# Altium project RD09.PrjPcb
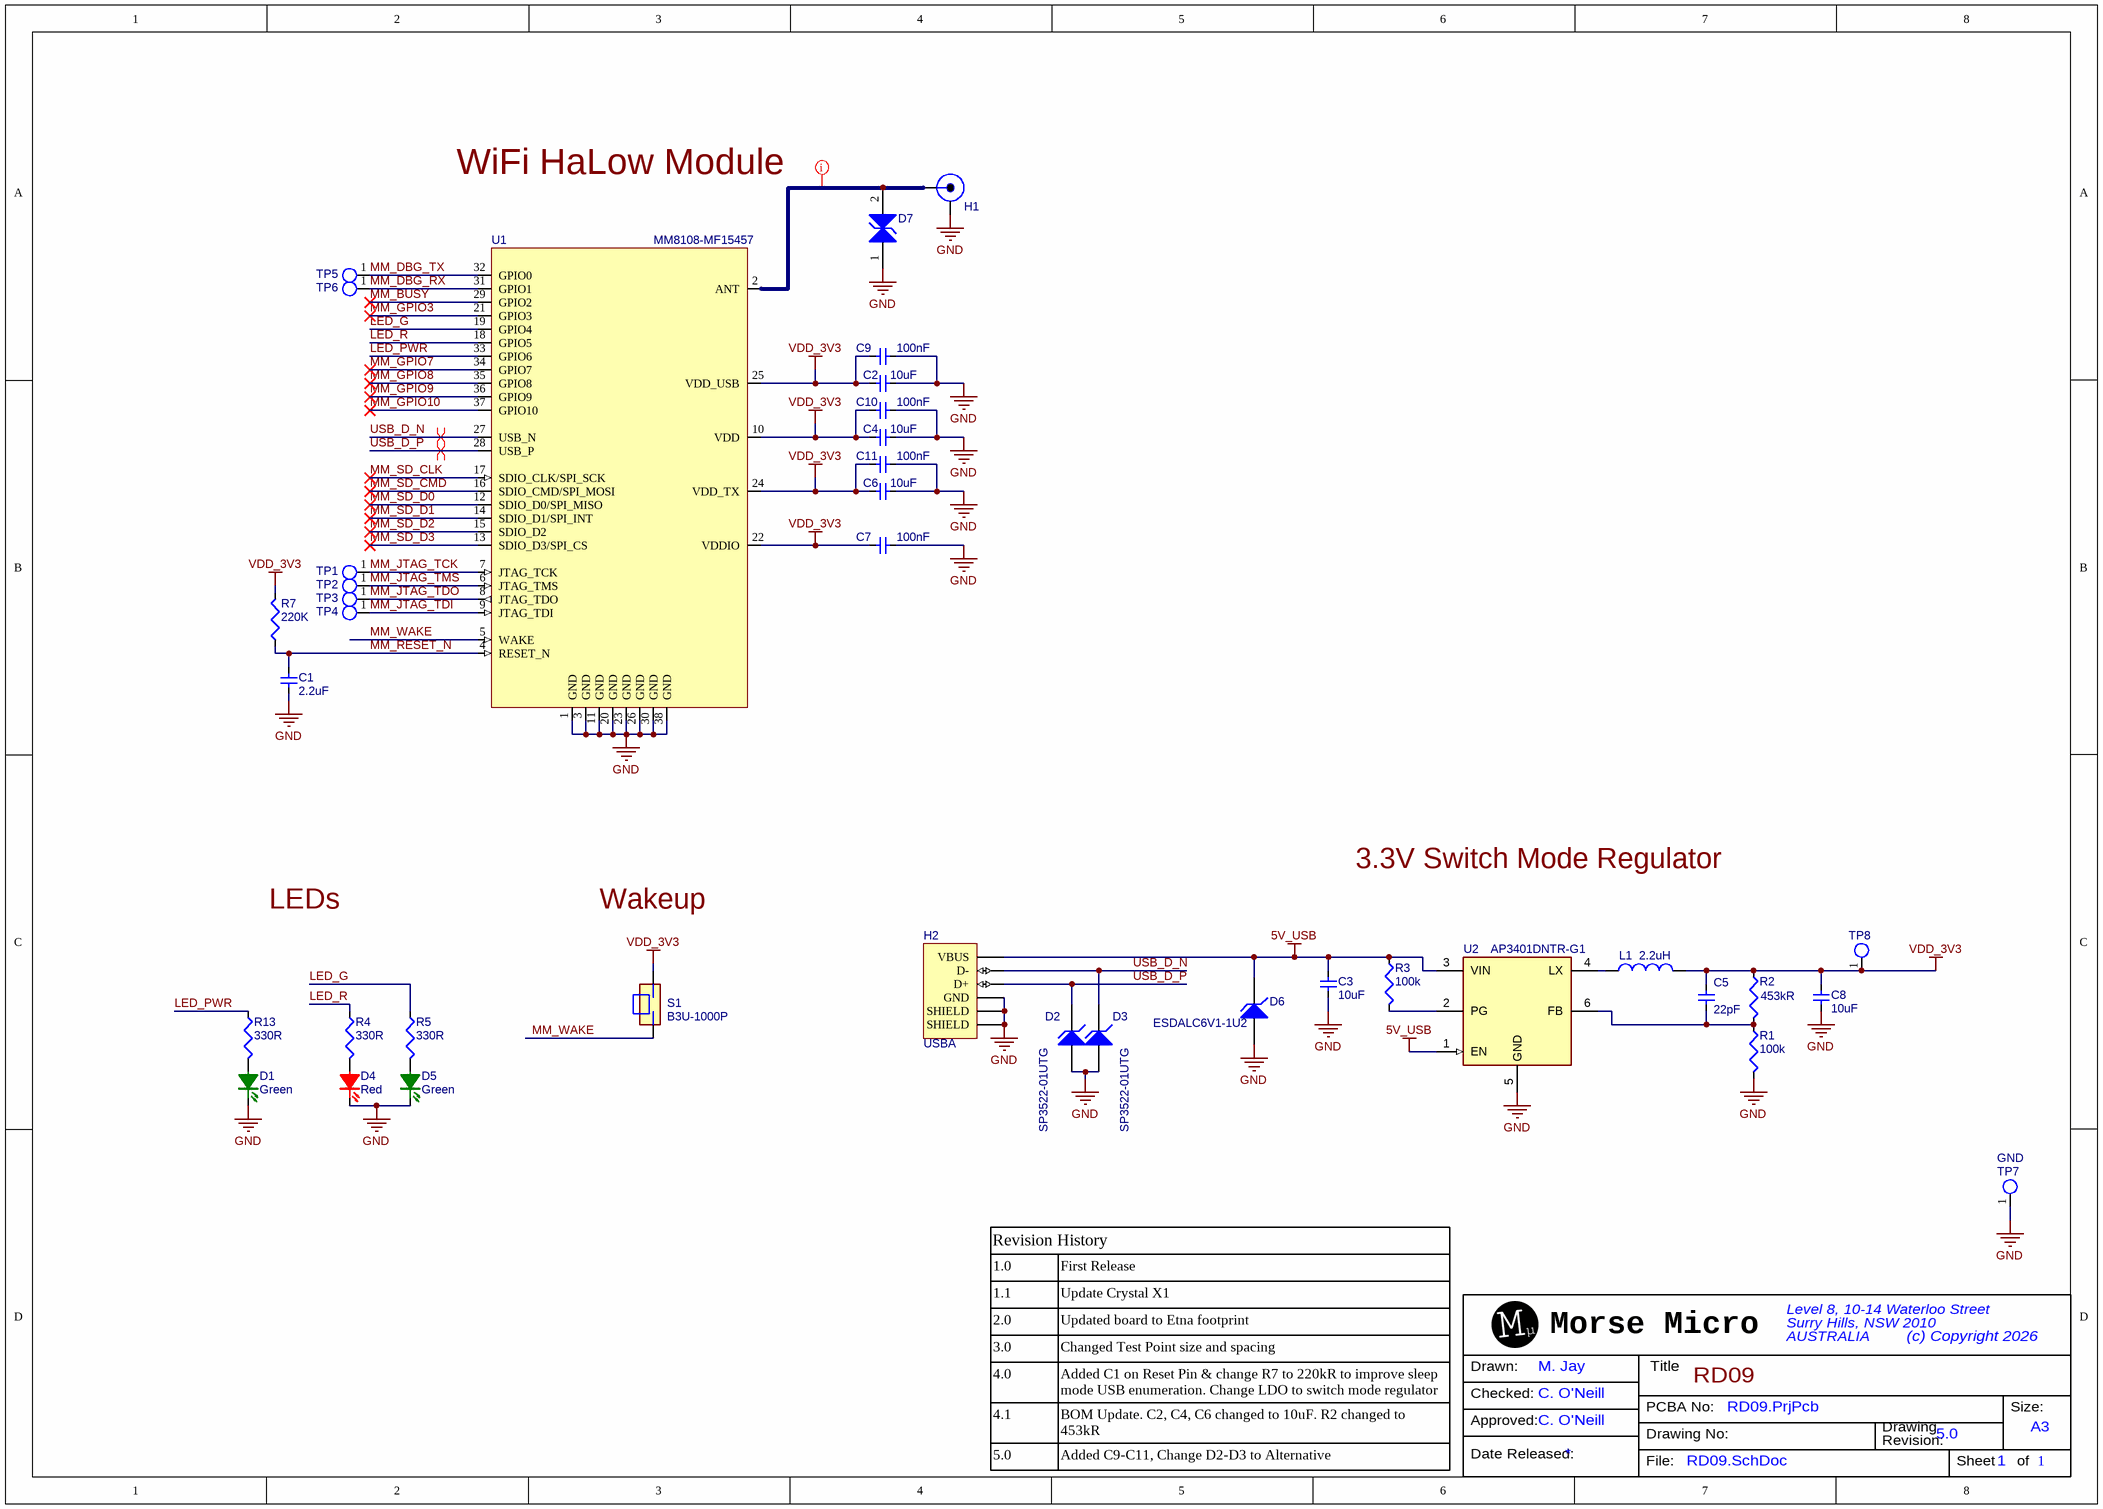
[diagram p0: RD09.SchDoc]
ApprovedBy: C. O'Neill; CheckedBy: C. O'Neill; DrawnBy: M. Jay; Project: RD09; Revision: 5.0
1 sheet, 39 parts. Net scope: global (net labels, ports and power ports of the same name join across sheets).
Board file: RD09.PcbDoc

## Sheet RD09.SchDoc: RD09
size A3; SheetNumber: 1; SheetTotal: 1; PageSetup: Record=PageOptions¦CenterHorizontal=True¦CenterVertical=True¦PrintScale=1.04¦XCorrection=1.00¦YCorrection=1.00¦PrintKind=0¦BorderSize=5000000¦LeftOffset=0¦BottomOffset=0¦Orientation=2¦PaperLength=1000¦PaperWidth=1000¦Scale=100¦PaperSource=7¦PrintQuality=-4¦MediaType=1¦DitherType=10¦PaperKind=A3¦PrintScaleMode=1

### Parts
C1  value 2.2uF  [0402_cap_rnd]  (hidden comment: GRM155R61E225ME15D)
C2  value 10uF  [0402_cap_rnd]  (hidden comment: CL05A106MP5NUNC)
C3  value 10uF  [0603_cap_rnd]  (hidden comment: GRM188R61E106MA73J)
C4  value 10uF  [0402_cap_rnd]  (hidden comment: CL05A106MP5NUNC)
C5  value 22pF  [0402_cap]  (hidden comment: CGA2B2NP01H220J050BA)
C6  value 10uF  [0402_cap_rnd]  (hidden comment: CL05A106MP5NUNC)
C7  value 100nF  [0402_cap_rnd]  (hidden comment: C0402C104K8RACTU)
C8  value 10uF  [0603_cap_rnd]  (hidden comment: GRM188R61E106MA73J)
C9  value 100nF  [0402_cap_rnd]  (hidden comment: C0402C104K8RACTU)
C10  value 100nF  [0402_cap_rnd]  (hidden comment: C0402C104K8RACTU)
C11  value 100nF  [0402_cap_rnd]  (hidden comment: C0402C104K8RACTU)
D1  value Green  [LED_0402_GREEN]  (hidden comment: XZVGR68W-3)
D2  SP3522-01UTG  [SP3522-01UTG-Footprint]
D3  SP3522-01UTG  [SP3522-01UTG-Footprint]
D4  value Red  [LED_0402_RED]  (hidden comment: LED_R)
D5  value Green  [LED_0402_GREEN]  (hidden comment: LED_G)
D6  ESDALC6V1-1U2  [0201_DIODE]
D7  ESD103B102ELE6327XTMA1  [INF-TSLP-2-20_V]  (value not drawn)
H1  142-0761-861  [SMA_EMERSON_142_0761_861]  (value not drawn)
H2  USBA  [USBA_BOARD_INLINE]
L1  value 2.2uH  [INDC2112X06N]  (hidden comment: LQM21PN2R2MGHL)
R1  value 100k  [0402_res_rnd]  (hidden comment: RC0402FR-07100KL)
R2  value 453kR  [0402_res]  (hidden comment: CRCW0402453KFKEDC)
R3  value 100k  [0402_res_rnd]  (hidden comment: RC0402FR-07100KL)
R4  value 330R  [0201_res_rnd]  (hidden comment: RES)
R5  value 330R  [0201_res_rnd]  (hidden comment: RES)
R7  value 220K  [0201_res_rnd]  (hidden comment: RC0201FR-07220KL)
R13  value 330R  [0201_res_rnd]  (hidden comment: RC0201FR-07330RL)
S1  B3U-1000P  [B3U-1000P]
TP1  PAD0035  [TP_40_SMT]  (value not drawn)
TP2  PAD0035  [TP_40_SMT]  (value not drawn)
TP3  PAD0035  [TP_40_SMT]  (value not drawn)
TP4  PAD0035  [TP_40_SMT]  (value not drawn)
TP5  PAD0035  [TP_40_SMT]  (value not drawn)
TP6  PAD0035  [TP_40_SMT]  (value not drawn)
TP7  PAD0035  [TP_40_SMT]  (value not drawn)
TP8  PAD0035  [TP_40_SMT]  (value not drawn)
U1  value MM8108-MF15457  [MF15]  (hidden comment: MM8108-MF15)
U2  AP3401DNTR-G1  [AP3401DNTR-G1-Footprint-1]

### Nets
5V_USB: C3.1 D6.K H2.1(VBUS) R3.1 U2.1(EN) U2.3(VIN)
GND: C1.2 C2.2 C3.2 C4.2 C6.2 C7.2 C8.2 C9.2 C10.2 C11.2 D1.K D2.A D3.A D4.K D5.K D6.A D7.1(C) H1.2 H2.4(GND) H2.5(SHIELD) H2.6(SHIELD) R1.2 TP7.1 U1.1(GND) U1.3(GND) U1.11(GND) U1.20(GND) U1.23(GND) U1.26(GND) U1.30(GND) U1.38(GND) U2.5(GND)
VDD_3V3: C2.1 C4.1 C5.1 C6.1 C7.1 C8.1 C9.1 C10.1 C11.1 L1.2 R2.1 R7.2 S1.2 TP8.1 U1.10(VDD) U1.22(VDDIO) U1.24(VDD_TX) U1.25(VDD_USB)
LED_G: R5.1 U1.19(GPIO4)
LED_PWR: R13.1 U1.33(GPIO6)
LED_R: R4.1 U1.18(GPIO5)
MM_BUSY: U1.29(GPIO2)
MM_DBG_RX: TP6.1 U1.31(GPIO1)
MM_DBG_TX: TP5.1 U1.32(GPIO0)
MM_GPIO3: U1.21(GPIO3)
MM_GPIO7: U1.34(GPIO7)
MM_GPIO8: U1.35(GPIO8)
MM_GPIO9: U1.36(GPIO9)
MM_GPIO10: U1.37(GPIO10)
MM_JTAG_TCK: TP1.1 U1.7(JTAG_TCK)
MM_JTAG_TDI: TP4.1 U1.9(JTAG_TDI)
MM_JTAG_TDO: TP3.1 U1.8(JTAG_TDO)
MM_JTAG_TMS: TP2.1 U1.6(JTAG_TMS)
MM_RESET_N: C1.1 R7.1 U1.4(RESET_N)
MM_SD_CLK: U1.17(SDIO_CLK/SPI_SCK)
MM_SD_CMD: U1.16(SDIO_CMD/SPI_MOSI)
MM_SD_D0: U1.12(SDIO_D0/SPI_MISO)
MM_SD_D1: U1.14(SDIO_D1/SPI_INT)
MM_SD_D2: U1.15(SDIO_D2)
MM_SD_D3: U1.13(SDIO_D3/SPI_CS)
MM_WAKE: S1.1 U1.5(WAKE)
USB_D_N: D3.K H2.2(D-) U1.27(USB_N)
USB_D_P: D2.K H2.3(D+) U1.28(USB_P)
NetC5_2: C5.2 R1.1 R2.2 U2.6(FB)
NetD1_A: D1.A R13.2
NetD4_A: D4.A R4.2
NetD5_A: D5.A R5.2
NetD7_2: D7.2(C) H1.1 U1.2(ANT)
NetL1_1: L1.1 U2.4(LX)
NetR3_2: R3.2 U2.2(PG)

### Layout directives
net class RF-Net: NetD7_2
differential pair; differential pair class DIFF_90: USB_D_N, USB_D_P

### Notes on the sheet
- WiFi HaLow Module
- LEDs
- Wakeup
- 3.3V Switch Mode Regulator
- (near TP7) GND
- Revision History
- 1.0
- 1.1
- First Release
- Update Crystal X1
- 2.0
- 3.0
- 4.0
- Updated board to Etna footprint
- Changed Test Point size and spacing
- Added C1 on Reset Pin & change R7 to 220kR to improve sleep mode USB enumeration. Change LDO to switch mode regulator
- 4.1
- BOM Update. C2, C4, C6 changed to 10uF. R2 changed to 453kR
- 5.0
- Added C9-C11, Change D2-D3 to Alternative

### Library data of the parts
C1 = CAP0055-14: CAP CER 2.2UF 25V ±20% X5R 0402; Generic Allowed: Yes; Subtype: Ceramic
C2 C4 C6 = CAP0268-1: Ceramic Capacitor, Multilayer, Ceramic, 10V, 20% +Tol, 20% -Tol, X5R, 15% TC, 10uF, Surface Mount, 0402; Generic Allowed: Yes
C3 C8 = CAP0197-10: CAP CER 10UF 25V ±20% X5R 0603; Subtype: Ceramic; Generic Allowed: Yes
C5 = CAP0017-14: CAP CER 22PF 50V ±5% C0G/NP0 0402; Generic Allowed: Yes; Subtype: Ceramic
C7 C9-C11 = CAP0025-15: CAP CER 100NF 10V ±10% X7R 0402; Generic Allowed: Yes; Subtype: Ceramic
D1 = DIO0053-7: LED GREEN 0402 SMD; Voltage: 2.0V; Generic Allowed: Yes
D2 D3 = DIO0091-2: ESD protection diodes / TVS diodes; LITTELFUSE; SP3522-01UTG; Surface Mount 0201
D4 = DIO0052-9: LED RED 0402 SMD; Generic Allowed: Yes; Voltage: 1.95V
D5 = DIO0053-7: LED GREEN 0402 SMD; Generic Allowed: Yes; Voltage: 2.0V
D6 = DIO0043-5: TVS DIODE 3VWM ST020; Generic Allowed: No; Voltage: 3V; Power: 20W
D7 = DIO0089-8: ESD103B102 Series 1 Line 15 V 0.2pF Bi-Direction TVS Protection Device-TSLP-2-20
H1 = JCK0001-4: Conn, SMA Jack 50 Ohm PCB Edge Mount Gold, RoHS; Generic Allowed: No
H2 = PLG0003-1: USB Connector, 4 Contact(s), Male, Right Angle, Surface Mount Terminal, Locking; Generic Allowed: YES
L1 = IND0084-2: FIXED IND 2.2uH 1.3A 156 MOHM 0805 ±20%; SubType: Multilayer; Generic Allowed: Yes
R1 R3 = RES0044-14: RES SMD 100K OHM ±1% 1/16W 0402; Generic Allowed: Yes
R2 = CMP-00022-3: Fixed Resistor, Metal Glaze/thick Film, 0.063W, 453000ohm, 50V, 1% +/-Tol, 100ppm/Cel, Surface Mount, 0402; Package Width: 0.5mm; Package Height: 0.3mm; Additional Feature: LASER TRIMMABLE; Temperature Coefficient (ppm/Cel): -100,100; Power: 63mW; Rated Temperature: 70°C; Package Length: 1mm
R4 R5 R13 = RES0020-12: RES SMD 330R OHM ±1% 1/20W 0201; Generic Allowed: Yes
R7 = RES0314-1: RES SMD 220K OHM ±1% 1/20W 0201; Generic Allowed: Yes
S1 = SWH0022-1: SWITCH TACTILE SPST-NO 0.05A 12V
TP1-TP8 = PAD0035-2: 40mil 1mm SMD Test Point; Shape: Round
U1 = MOD0024-12: Generic Allowed: No
U2 = CMP-00018-3: Switching Regulator, Current-mode, 1500kHz Switching Freq-Max, PDSO6

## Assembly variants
Default Build: not fitted S1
